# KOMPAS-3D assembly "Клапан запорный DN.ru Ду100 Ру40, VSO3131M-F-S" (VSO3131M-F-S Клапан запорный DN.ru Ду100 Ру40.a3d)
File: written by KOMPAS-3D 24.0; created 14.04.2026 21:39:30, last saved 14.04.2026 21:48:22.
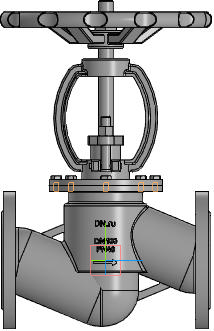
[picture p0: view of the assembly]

Document properties: Автор: R2D2; Полное имя файла: E:\Работа\Зайцев\VSO3131M-F-S Клапан запорный DN.ru Ду15-100 Ру40\DN100\исходные материалы\VSO3131M-F-S Клапан запорный DN.ru Ду100 Ру40.a3d

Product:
- Component [detail]: Корпус  | qty 1  | pos. 1  | Масса: 6.9; Автор: R2D2; source file: Корпус.m3d
- Component [detail]: Клапан запорный DN.ru Ду100 Ру16  | designation VSO1121M-F-S  | qty 1  | pos. 2  | Масса: 38.27; Раздел спецификации: Прочие изделия; Примечание: D090-01950; Автор: R2D2; source file: 2.m3d
- Part/product: Клапан запорный DN.ru Ду100 Ру40  | designation VSO3131M-F-S
    Масса: 36.7
    Раздел спецификации: Прочие изделия
    Примечание: D090-02145

Referenced files in E:\Работа\Зайцев\VSO3131M-F-S Клапан запорный DN.ru Ду15-100 Ру40\DN100\исходные материалы\: Корпус.m3d, 2.m3d
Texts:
  VSO3131M-F-S
  VSO1121M-F-S Клапан запорный DN.ru Ду100 Ру16
  Ось Y.Начало координат
  Плоскость ZY.Начало координат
